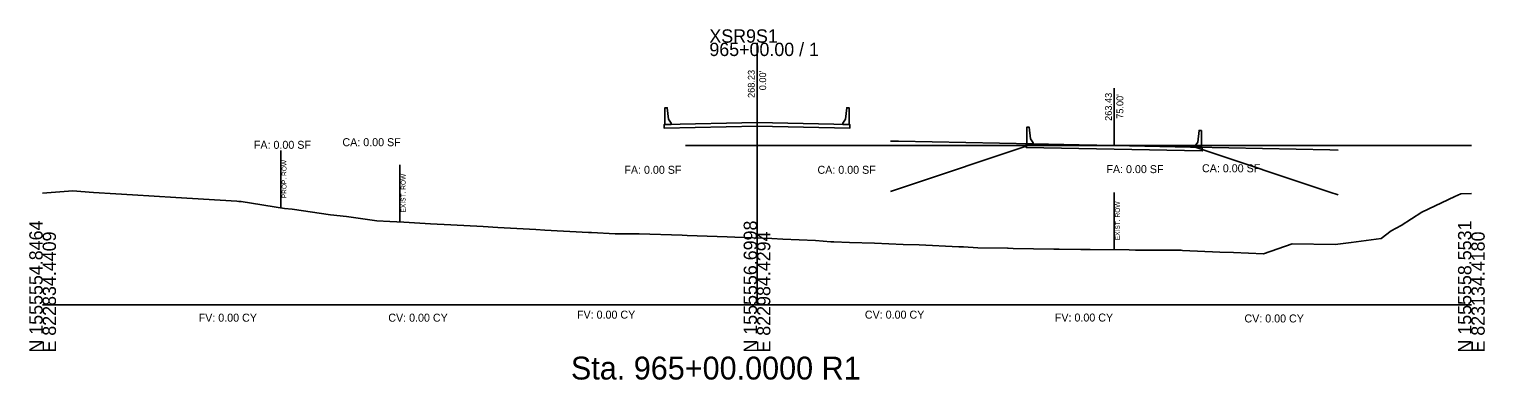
# Model space of a CAD drawing. Extents: x -26 to 823017, y -16 to 1558356.
# Drawn here: x 997.2 to 1302.8, y 4484.3 to 4557.8 of the extents above; entities that cross this region are included whole.
import ezdxf

# ---------------------------------------------------------------- set-up
doc = ezdxf.new("R2010")
doc.units = 0
for name, color, linetype in [('CONST_LV3', 7, 'Continuous'), ('Draft_XS_Grid', 7, 'Continuous'), ('Draft_XS_Text', 7, 'Continuous'), ('DTM_TEMP_DROP', 7, 'Continuous'), ('DTM_X_GROUND', 7, 'Continuous'), ('XS_CELL', 7, 'Continuous'), ('XS_P_CONCRETE', 7, 'Continuous'), ('XS_P_ROW', 7, 'Continuous'), ('XS_P_TX_CLEARZONE', 7, 'Continuous'), ('XS_SHEET_EW_TX_AREA', 7, 'Continuous'), ('XS_SHEET_EW_TX_VOLUME', 7, 'Continuous'), ('XS_X_ROW', 7, 'Continuous')]:
    doc.layers.add(name, color=color, linetype=linetype)

msp = doc.modelspace()

# ---------------------------------------------------------------- linework, layer by layer
at = {"layer": 'CONST_LV3'}
for points in [[(1135, 4533.43), (1145.38, 4533.43), (1300, 4533.43)], [(1178, 4534.37), (1179.73, 4534.33), (1208, 4533.77), (1224.02, 4533.45), (1225, 4533.43), (1241.02, 4533.11), (1242, 4533.09), (1270.27, 4532.52), (1272, 4532.49)], [(1178, 4523.77), (1179.73, 4524.34), (1208, 4533.77), (1224.02, 4533.45), (1225, 4533.43), (1241.02, 4533.11), (1242, 4533.09), (1270.27, 4523.66), (1272, 4523.09)], [(1000, 4523.42), (1006.32, 4523.9), (1008.04, 4523.79), (1010.7, 4523.61), (1015.4, 4523.3), (1018.84, 4523.08), (1028, 4522.52), (1040.75, 4521.73), (1041.18, 4521.7), (1041.65, 4521.67), (1050.77, 4520.24), (1052.4, 4520.07), (1060.47, 4518.87), (1063.8, 4518.54), (1070.18, 4517.64), (1072.91, 4517.49), (1075.87, 4517.33), (1081.44, 4517.02), (1085.73, 4516.8), (1092.49, 4516.42), (1095.58, 4516.26), (1103.56, 4515.81), (1105.43, 4515.71), (1114.64, 4515.2), (1115.27, 4515.16), (1120.24, 4514.88), (1125.04, 4514.91), (1125.24, 4514.9), (1134.28, 4514.63), (1135.31, 4514.57), (1143.74, 4514.3), (1145.37, 4514.19), (1153.08, 4513.93), (1155.45, 4513.76), (1162.29, 4513.51), (1165.52, 4513.25), (1166.14, 4513.23), (1169.39, 4513.1), (1174.67, 4512.97), (1180.72, 4512.69), (1184.08, 4512.61), (1192.38, 4512.19), (1193.33, 4512.16), (1196.37, 4511.98), (1202.63, 4511.89), (1202.74, 4511.89), (1203.82, 4511.86), (1212.35, 4511.71), (1213.43, 4511.68), (1217.98, 4511.65), (1219.93, 4511.59), (1228.12, 4511.55), (1229.5, 4511.51), (1238.25, 4511.48), (1239.08, 4511.46), (1239.38, 4511.44), (1247.15, 4511.07), (1250.06, 4510.99), (1256.32, 4510.71), (1262.38, 4512.8), (1271.43, 4512.67), (1274.74, 4513.1), (1281.06, 4513.92), (1283.15, 4515.54), (1285.26, 4516.66), (1289.59, 4519.48), (1296.56, 4522.74), (1297.76, 4523.3), (1300, 4523.4)]]:
    msp.add_lwpolyline(points, dxfattribs=at)
at = {"layer": 'DTM_X_GROUND'}
msp.add_lwpolyline([(1000, 4523.42), (1006.32, 4523.9), (1008.04, 4523.79), (1010.7, 4523.61), (1015.4, 4523.3), (1018.84, 4523.08), (1028, 4522.52), (1040.75, 4521.73), (1041.18, 4521.7), (1041.65, 4521.67), (1050.77, 4520.24), (1052.4, 4520.07), (1060.47, 4518.87), (1063.8, 4518.54), (1070.18, 4517.64), (1072.91, 4517.49), (1075.87, 4517.33), (1081.44, 4517.02), (1085.73, 4516.8), (1092.49, 4516.42), (1095.58, 4516.26), (1103.56, 4515.81), (1105.43, 4515.71), (1114.64, 4515.2), (1115.27, 4515.16), (1120.24, 4514.88), (1125.04, 4514.91), (1125.24, 4514.9), (1134.28, 4514.63), (1135.31, 4514.57), (1143.74, 4514.3), (1145.37, 4514.19), (1153.08, 4513.93), (1155.45, 4513.76), (1162.29, 4513.51), (1165.52, 4513.25), (1166.14, 4513.23), (1169.39, 4513.1), (1174.67, 4512.97), (1180.72, 4512.69), (1184.08, 4512.61), (1192.38, 4512.19), (1193.33, 4512.16), (1196.37, 4511.98), (1202.63, 4511.89), (1202.74, 4511.89), (1203.82, 4511.86), (1212.35, 4511.71), (1213.43, 4511.68), (1217.98, 4511.65), (1219.93, 4511.59), (1228.12, 4511.55), (1229.5, 4511.51), (1238.25, 4511.48), (1239.08, 4511.46), (1239.38, 4511.44), (1247.15, 4511.07), (1250.06, 4510.99), (1256.32, 4510.71), (1262.38, 4512.8), (1271.43, 4512.67), (1274.74, 4513.1), (1281.06, 4513.92), (1283.15, 4515.54), (1285.26, 4516.66), (1289.59, 4519.48), (1296.56, 4522.74), (1297.76, 4523.3), (1300, 4523.4)], dxfattribs=at)
at = {"layer": 'XS_CELL'}
for p, q in [((1150, 4500), (1150, 4555)), ((1000, 4500), (1150, 4500)), ((1150, 4500), (1300, 4500))]:
    msp.add_line(p, q, dxfattribs=at)
at = {"layer": 'XS_P_CONCRETE'}
for points in [[(1130.67, 4537.85), (1130.67, 4541.35), (1131.17, 4541.37), (1131.42, 4538.96), (1132, 4538.12), (1132, 4537.87), (1130.67, 4537.85)], [(1168, 4537.87), (1168, 4538.12), (1168.58, 4538.96), (1168.83, 4541.37), (1169.33, 4541.35), (1169.33, 4537.85), (1168, 4537.87)], [(1150, 4538.23), (1169.33, 4537.85), (1169.5, 4537.84), (1169.5, 4537.09), (1150, 4537.48), (1130.5, 4537.09), (1130.5, 4537.84), (1130.67, 4537.85), (1150, 4538.23)], [(1206.67, 4533.79), (1206.67, 4537.29), (1207.17, 4537.27), (1207.42, 4534.85), (1208, 4534.02), (1208, 4533.77), (1206.67, 4533.79)], [(1243.33, 4533.06), (1243.33, 4536.56), (1242.83, 4536.59), (1242.58, 4534.17), (1242, 4533.34), (1242, 4533.09), (1243.33, 4533.06)], [(1225, 4533.43), (1243.33, 4533.06), (1243.5, 4533.06), (1243.5, 4532.31), (1225, 4532.68), (1206.5, 4533.05), (1206.5, 4533.8), (1206.67, 4533.79), (1225, 4533.43)]]:
    msp.add_lwpolyline(points, dxfattribs=at)
at = {"layer": 'XS_P_ROW'}
msp.add_line((1050, 4520.36), (1050, 4532.36), dxfattribs=at)
at = {"layer": 'XS_P_TX_CLEARZONE'}
for p, q in [((1150, 4538.23), (1150, 4550.23)), ((1225, 4533.43), (1225, 4545.43))]:
    msp.add_line(p, q, dxfattribs=at)
at = {"layer": 'XS_X_ROW'}
for p, q in [((1075, 4517.38), (1075, 4529.38)), ((1225, 4511.57), (1225, 4523.57))]:
    msp.add_line(p, q, dxfattribs=at)

# ---------------------------------------------------------------- texts
at = {"layer": 'Draft_XS_Grid'}
msp.add_text('-', height=0.0001, dxfattribs=at).set_placement((1000, 4500))
at = {"layer": 'Draft_XS_Text'}
msp.add_text('Sta. 965+00.0000 R1', height=4.8, dxfattribs=at).set_placement((1110.92, 4484.35))
at = {"layer": 'DTM_TEMP_DROP'}
for p in [(1149.92, 4538.11), (1224.92, 4533.31)]:
    msp.add_text('X', height=0.24, dxfattribs=at).set_placement(p)
at = {"layer": 'XS_CELL'}
for s, p in [('XSR9S1', (1140, 4555)), ('965+00.00 / 1', (1140, 4552.2))]:
    msp.add_text(s, height=2.8, dxfattribs=at).set_placement(p)
for s, p in [('N 1555554.8464', (1000, 4490)), ('E 822834.4409', (1002.8, 4490)), ('N 1555556.6998', (1150, 4490)), ('E 822984.4294', (1152.8, 4490)), ('N 1555558.5531', (1300, 4490)), ('E 823134.4180', (1302.8, 4490))]:
    msp.add_text(s, height=2.8, rotation=90, dxfattribs=at).set_placement(p)
at = {"layer": 'XS_P_ROW'}
msp.add_text('PROP. ROW', height=1, rotation=90, dxfattribs=at).set_placement((1051.2, 4522.36))
at = {"layer": 'XS_P_TX_CLEARZONE'}
for s, p in [('268.23', (1149.52, 4543.41)), ("0.00'", (1151.92, 4545.02)), ('263.43', (1224.52, 4538.6)), ("75.00'", (1226.92, 4539.04))]:
    msp.add_text(s, height=1.44, rotation=90, dxfattribs=at).set_placement(p)
at = {"layer": 'XS_SHEET_EW_TX_AREA'}
for s, p in [('FA: 0.00 SF', (1044.35, 4532.74)), ('CA: 0.00 SF', (1062.95, 4533.29)), ('FA: 0.00 SF', (1122.15, 4527.5)), ('CA: 0.00 SF', (1162.7, 4527.5)), ('FA: 0.00 SF', (1223.37, 4527.64)), ('CA: 0.00 SF', (1243.44, 4527.82))]:
    msp.add_text(s, height=1.68, dxfattribs=at).set_placement(p)
at = {"layer": 'XS_SHEET_EW_TX_VOLUME'}
for s, p in [('FV: 0.00 CY', (1032.76, 4496.48)), ('CV: 0.00 CY', (1072.58, 4496.48)), ('FV: 0.00 CY', (1112.2, 4497.12)), ('CV: 0.00 CY', (1172.65, 4497.12)), ('FV: 0.00 CY', (1212.54, 4496.51)), ('CV: 0.00 CY', (1252.35, 4496.32))]:
    msp.add_text(s, height=1.68, dxfattribs=at).set_placement(p)
at = {"layer": 'XS_X_ROW'}
for p in [(1076.2, 4519.38), (1226.2, 4513.57)]:
    msp.add_text('EXIST. ROW', height=1, rotation=90, dxfattribs=at).set_placement(p)

doc.saveas('drawing.dxf')
